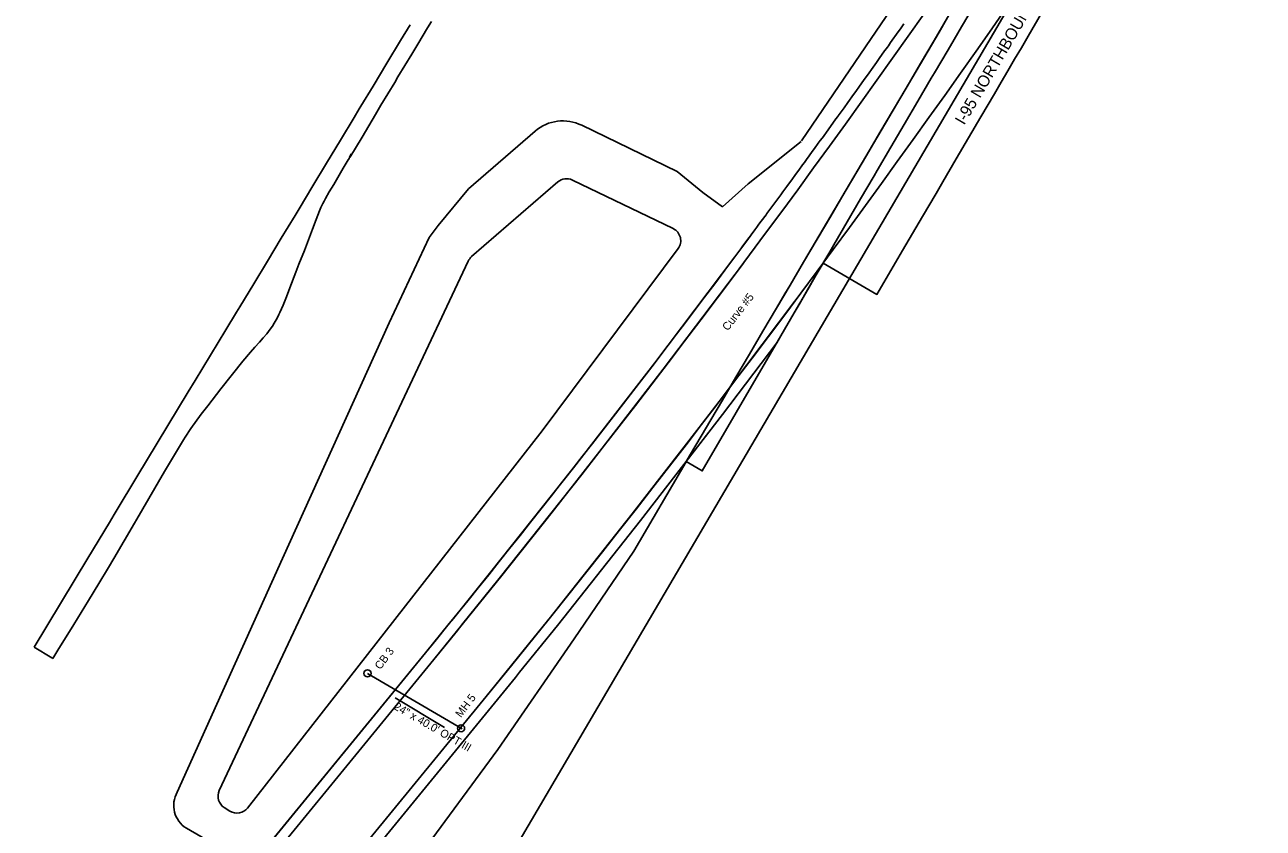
# Model space of a CAD drawing. Extents: x 1160458 to 1162290, y 615427 to 618737.
# Drawn here: x 1161573.3 to 1162037.4, y 617839 to 618140.3 of the extents above; entities that cross this region are included whole.
import ezdxf

# ---------------------------------------------------------------- set-up
doc = ezdxf.new("R2010")
doc.units = 0
for name, color, linetype in [('1', 7, 'Continuous'), ('ANNOTATION', 7, 'Continuous'), ('D_Drainage_Culvert', 7, 'Continuous'), ('D_Drainage_Ditch_Line', 7, 'Continuous'), ('D_Drainage_MH', 7, 'Continuous'), ('D_Drainage_Text', 7, 'Continuous'), ('D_Guardrail_Beam_Lt', 7, 'Continuous'), ('D_Roadway_Edge_Pavement', 7, 'Continuous'), ('D_Roadway_Edge_Shoulder', 7, 'Continuous'), ('D_Roadway_Edge_TW', 7, 'Continuous'), ('D_Slope_Cut', 7, 'Continuous'), ('D_Slope_Fill', 7, 'Continuous'), ('D_Text_Standard', 7, 'Continuous'), ('Old pavement area_not used', 7, 'Continuous'), ('Shoulder work for div plan (NB)', 7, 'Continuous'), ('Shoulder work for div plans (SB)', 7, 'Continuous')]:
    doc.layers.add(name, color=color, linetype=linetype)

msp = doc.modelspace()

# ---------------------------------------------------------------- linework, layer by layer
at = {"layer": '1'}
msp.add_line((1161209.81, 616899.51), (1162286.6, 618733.81), dxfattribs=at)
at = {"layer": 'D_Drainage_Culvert'}
msp.add_line((1161701.71, 617897.08), (1161737.14, 617876.33), dxfattribs=at)
at = {"layer": 'D_Drainage_Ditch_Line'}
for p, q in [((1161740.72, 618053.31), (1161773.05, 618081.31)), ((1161778.49, 618082.04), (1161816.28, 618063.82)), ((1161646.17, 617853.13), (1161739.47, 618051.66)), ((1161650.16, 617845.44), (1161648.04, 617846.77))]:
    msp.add_line(p, q, dxfattribs=at)
msp.add_lwpolyline([(1161818.11, 618056.33), (1161767.17, 617987.95), (1161656.76, 617846.59)], dxfattribs=at)
for centre, start, end in [((1161776.32, 618077.53), 64.2558, 130.8964), ((1161814.1, 618059.32), 323.3125, 64.2558), ((1161743.99, 618049.53), 130.8964, 154.8308), ((1161650.7, 617851), 154.8308, 237.8219), ((1161652.82, 617849.67), 237.8219, 322.0086)]:
    msp.add_arc(centre, 5, start, end, dxfattribs=at)
at = {"layer": 'D_Drainage_MH'}
for centre in [(1161701.71, 617897.08), (1161736.79, 617876.49)]:
    msp.add_circle(centre, 1.33, dxfattribs=at)
at = {"layer": 'D_Guardrail_Beam_Lt'}
msp.add_line((1161723.42, 617904.81), (1161637.37, 617799.61), dxfattribs=at)
msp.add_arc((1158484.81, 620553.82), 4184, 320.71863, 323.46992, dxfattribs=at)
at = {"layer": 'D_Roadway_Edge_Pavement'}
msp.add_line((1161872.48, 618050.9), (1161892.62, 618039.13), dxfattribs=at)
for points in [[(1161637.38, 617799.61), (1161723.43, 617904.81), (1161732.32, 617915.72), (1161733.89, 617917.65), (1161747.97, 617935.1), (1161778.91, 617974.13), (1161809.39, 618013.53), (1161839.39, 618053.29)], [(1161618.68, 617724.81), (1161646.49, 617760.08), (1161649.61, 617763.95), (1161650.23, 617764.73), (1161662.12, 617779.35), (1161748.17, 617884.56), (1161757.13, 617895.56), (1161758.72, 617897.51), (1161772.9, 617915.08), (1161804.08, 617954.41), (1161834.79, 617994.11), (1161855.07, 618020.99)]]:
    msp.add_lwpolyline(points, dxfattribs=at)
at = {"layer": 'D_Roadway_Edge_Shoulder'}
msp.add_lwpolyline([(1161837.36, 618050.57), (1161838.6, 618052.24), (1161839.39, 618053.3), (1161841.21, 618055.74), (1161841.61, 618056.28), (1161842.4, 618057.35), (1161844.61, 618060.31), (1161845.07, 618060.93), (1161845.41, 618061.39), (1161847.6, 618064.36), (1161848.4, 618065.44), (1161850.59, 618068.39), (1161851.06, 618069.03), (1161851.4, 618069.49), (1161852.85, 618071.46), (1161853.58, 618072.45), (1161854.39, 618073.54), (1161856.56, 618076.49), (1161857.36, 618077.59), (1161858.81, 618079.57), (1161859.53, 618080.55), (1161860.34, 618081.65), (1161862.5, 618084.6), (1161863.31, 618085.71), (1161864.75, 618087.69), (1161865.47, 618088.67), (1161866.28, 618089.78), (1161867.24, 618091.1), (1161868.42, 618092.73), (1161869.23, 618093.84), (1161870.67, 618095.82), (1161871.38, 618096.8), (1161872.09, 618097.77), (1161872.19, 618097.92), (1161874.33, 618100.87), (1161877.28, 618104.94), (1161877.98, 618105.92), (1161878.09, 618106.07), (1161880.3, 618109.13), (1161881.76, 618111.16), (1161883.85, 618114.08), (1161884.7, 618115.26), (1161886.16, 618117.29), (1161887.61, 618119.32), (1161889.7, 618122.25), (1161890.55, 618123.43), (1161892.46, 618126.12), (1161893.5, 618127.58), (1161895.53, 618130.43), (1161895.62, 618130.56), (1161896.57, 618131.89), (1161896.92, 618132.39), (1161897.74, 618133.55), (1161900.64, 618137.64), (1161901.43, 618138.75), (1161902.72, 618140.58)], dxfattribs=at)
at = {"layer": 'D_Roadway_Edge_TW'}
for points in [[(1161640.47, 617797.08), (1161726.52, 617902.28), (1161735.42, 617913.2), (1161736.99, 617915.14), (1161751.08, 617932.6), (1161782.05, 617971.67), (1161812.56, 618011.1), (1161842.58, 618050.88)], [(1161659.04, 617781.88), (1161745.09, 617887.08), (1161754.05, 617898.07), (1161755.62, 617900.01), (1161769.79, 617917.57), (1161800.95, 617956.87), (1161831.63, 617996.53), (1161861.85, 618036.57)]]:
    msp.add_lwpolyline(points, dxfattribs=at)
for radius in [4188, 4212]:
    msp.add_arc((1158484.81, 620553.82), radius, 320.71863, 329.58575, dxfattribs=at)
at = {"layer": 'D_Slope_Cut'}
for p, q in [((1161834.79, 618072.02), (1161844.39, 618080.57)), ((1161633.82, 617839.01), (1161646.1, 617831.93))]:
    msp.add_line(p, q, dxfattribs=at)
for points in [[(1161764.53, 618100.39), (1161739.5, 618078.71), (1161728.2, 618064.96), (1161724.84, 618060.51), (1161709.79, 618028.48), (1161669.91, 617940.09), (1161630.43, 617852.53)], [(1161834.79, 618072.02), (1161827.35, 618077.35), (1161817.81, 618085.28), (1161781.98, 618102.56)]]:
    msp.add_lwpolyline(points, dxfattribs=at)
for centre, radius, start, end in [((1161774.9, 618088.21), 16, 63.7426, 130.4032), ((1161639.16, 617847.54), 10.06, 150.2229, 237.9775)]:
    msp.add_arc(centre, radius, start, end, dxfattribs=at)
at = {"layer": 'D_Slope_Fill'}
msp.add_line((1161864.23, 618096.46), (1161844.39, 618080.57), dxfattribs=at)
for points in [[(1161864.33, 618096.78), (1161892.38, 618137.82), (1161920.38, 618178.92), (1161947.2, 618220.79), (1161974.76, 618262.22), (1162003.5, 618302.78), (1162031.65, 618343.82), (1162058.74, 618385.58), (1162080.66, 618419.35), (1162091.79, 618436.2), (1162091.79, 618436.2)], [(1161467.62, 617462.59), (1161495.86, 617503), (1161520.87, 617545.48), (1161546.51, 617587.64), (1161578.88, 617625.09), (1161605.67, 617666.51), (1161619.85, 617717.84), (1161649.13, 617757.97), (1161681.16, 617796.15), (1161720.89, 617828.25), (1161750.61, 617868.53), (1161779.17, 617910.05), (1161801.48, 617942.93), (1161821.11, 617976.43)]]:
    msp.add_lwpolyline(points, dxfattribs=at)
at = {"layer": 'D_Text_Standard'}
msp.add_line((1161712.08, 617887.96), (1161730.57, 617876.83), dxfattribs=at)
at = {"layer": 'Old pavement area_not used'}
for points in [[(1161919.14, 618142.92), (1161914.07, 618134.3), (1161908.99, 618125.68), (1161903.92, 618117.07), (1161898.84, 618108.45), (1161893.76, 618099.84), (1161888.69, 618091.22), (1161885.45, 618085.73), (1161880.37, 618077.11), (1161875.3, 618068.5), (1161870.22, 618059.88), (1161865.15, 618051.26), (1161860.07, 618042.65), (1161855, 618034.03), (1161849.93, 618025.41), (1161844.85, 618016.79), (1161839.78, 618008.18), (1161834.71, 617999.56), (1161830.36, 617992.17), (1161821.12, 617976.45)], [(1161855.09, 618021.01), (1161856.62, 618023.65), (1161861.65, 618032.3), (1161866.68, 618040.94), (1161869.91, 618046.49), (1161872.48, 618050.9), (1161892.62, 618039.13), (1161902.25, 618055.61), (1161909.73, 618068.41), (1161914.79, 618077.04), (1161917.31, 618081.35), (1161922.36, 618089.98), (1161926.98, 618097.88), (1161931.61, 618105.77), (1161936.66, 618114.4), (1161939.19, 618118.71), (1161941.71, 618123.02), (1161944.24, 618127.34), (1161946.77, 618131.65), (1161949.3, 618135.97), (1161954.35, 618144.59)], [(1161821.12, 617976.45), (1161834.8, 617994.12), (1161855.09, 618021.01)]]:
    msp.add_lwpolyline(points, dxfattribs=at)
at = {"layer": 'Shoulder work for div plan (NB)'}
msp.add_line((1161921.57, 618134.78), (1161921.57, 618134.78), dxfattribs=at)
for points in [[(1162008.98, 618296.98), (1162007.84, 618295), (1162002.84, 618286.34), (1161997.84, 618277.68), (1161992.87, 618269.04), (1161987.86, 618260.38), (1161985.49, 618256.3), (1161980.47, 618247.65), (1161975.44, 618239.01), (1161970.4, 618230.37), (1161968.95, 618227.89), (1161963.91, 618219.25), (1161958.86, 618210.62), (1161953.81, 618201.98), (1161948.76, 618193.35), (1161946.83, 618190.06), (1161941.78, 618181.44), (1161936.72, 618172.81), (1161933.64, 618167.57), (1161928.57, 618158.95), (1161923.5, 618150.33), (1161919.14, 618142.92), (1161915.96, 618137.52)], [(1161921.57, 618134.78), (1161924.35, 618139.51), (1161929.4, 618148.14)], [(1161915.96, 618137.52), (1161891.35, 618095.75), (1161866.74, 618053.97)], [(1161872.38, 618050.74), (1161874.93, 618055.11), (1161876.44, 618057.7), (1161881.48, 618066.34), (1161886.53, 618074.97), (1161891.57, 618083.6), (1161892.78, 618085.67), (1161897.83, 618094.3), (1161902.89, 618102.92), (1161907.95, 618111.55), (1161913.01, 618120.18), (1161914.22, 618122.25), (1161919.28, 618130.87), (1161921.57, 618134.78)], [(1161866.74, 618053.97), (1161865.15, 618051.26), (1161860.07, 618042.65), (1161858.12, 618039.32)], [(1161863.43, 618035.36), (1161866.66, 618040.93), (1161869.9, 618046.47), (1161872.38, 618050.74)], [(1161858.12, 618039.32), (1161855, 618034.03), (1161849.93, 618025.41), (1161844.85, 618016.79), (1161839.78, 618008.18), (1161834.71, 617999.56), (1161830.36, 617992.17), (1161821.12, 617976.45)], [(1161852.58, 618016.69), (1161856.61, 618023.64), (1161861.64, 618032.28), (1161863.43, 618035.36)], [(1161821.12, 617976.45), (1161827.14, 617972.95), (1161852.58, 618016.69)]]:
    msp.add_lwpolyline(points, dxfattribs=at)
at = {"layer": 'Shoulder work for div plans (SB)'}
for p, q in [((1161724.24, 618139.12), (1161725.69, 618141.52)), ((1161720.52, 618132.96), (1161724.24, 618139.12)), ((1161706.76, 618110.09), (1161711.91, 618118.67)), ((1161698.63, 618108.69), (1161696.72, 618105.52)), ((1161699.26, 618109.72), (1161698.63, 618108.69)), ((1161704.7, 618106.64), (1161706.76, 618110.09)), ((1161696.72, 618105.52), (1161691.56, 618096.95)), ((1161699.65, 618098.15), (1161704.7, 618106.64)), ((1161691.56, 618096.95), (1161686.4, 618088.39)), ((1161695.05, 618090.44), (1161699.65, 618098.15)), ((1161695.64, 618091.85), (1161695.05, 618090.44)), ((1161695.38, 618091.41), (1161695.64, 618091.85)), ((1161686.4, 618088.39), (1161681.24, 618079.83)), ((1161689.04, 618080.39), (1161692.65, 618086.44)), ((1161692.65, 618086.44), (1161694.52, 618089.56)), ((1161694.52, 618089.56), (1161694.64, 618089.76)), ((1161681.24, 618079.83), (1161676.07, 618071.26)), ((1161686.01, 618075.17), (1161687.4, 618077.6)), ((1161687.4, 618077.6), (1161689.04, 618080.39)), ((1161684.96, 618073.24), (1161685.43, 618074.14)), ((1161685.43, 618074.14), (1161686.01, 618075.17)), ((1161669.41, 618060.23), (1161664.24, 618051.67)), ((1161676.01, 618050.48), (1161678.04, 618055.63)), ((1161667.48, 618029.57), (1161667.83, 618030.22)), ((1161659.51, 618019.37), (1161661.21, 618021.27)), ((1161661.21, 618021.27), (1161662.6, 618022.84)), ((1161657.87, 618017.53), (1161659.51, 618019.37)), ((1161641.82, 617997.4), (1161646.71, 618003.73)), ((1161639.41, 617994.29), (1161641.82, 617997.4)), ((1161625.68, 617972.76), (1161632.7, 617984.59)), ((1161615.32, 617970.77), (1161607.57, 617957.93)), ((1161619.77, 617962.67), (1161625.68, 617972.76)), ((1161615.28, 617954.92), (1161619.77, 617962.67)), ((1161607.57, 617957.93), (1161607.57, 617957.93)), ((1161614.4, 617953.41), (1161615.28, 617954.92)), ((1161585.69, 617905.74), (1161591.61, 617915.36)), ((1161576.79, 617906.86), (1161583.42, 617902.88)), ((1161583.78, 617902.66), (1161585.69, 617905.74)), ((1161583.42, 617902.88), (1161583.78, 617902.66))]:
    msp.add_line(p, q, dxfattribs=at)
for points in [[(1161717.68, 618140.26), (1161714.13, 618134.38), (1161708.96, 618125.81)], [(1161711.91, 618118.67), (1161713.11, 618120.67), (1161718.27, 618129.24), (1161720.52, 618132.96)], [(1161708.96, 618125.81), (1161703.8, 618117.25), (1161699.26, 618109.72)], [(1161682.52, 618067.27), (1161683.69, 618070.45), (1161684.24, 618071.76), (1161684.96, 618073.24)], [(1161676.07, 618071.26), (1161674.58, 618068.79), (1161669.41, 618060.23)], [(1161678.04, 618055.63), (1161681.14, 618063.6), (1161682.52, 618067.27)], [(1161664.24, 618051.67), (1161659.07, 618043.12), (1161653.89, 618034.56)], [(1161671.36, 618038.28), (1161672.64, 618041.57), (1161674.86, 618047.46), (1161676.01, 618050.48)], [(1161653.89, 618034.56), (1161652.64, 618032.49), (1161648.67, 618025.93)], [(1161667.83, 618030.22), (1161668.54, 618031.64), (1161668.91, 618032.43), (1161669.49, 618033.72), (1161670.09, 618035.14), (1161671.36, 618038.28)], [(1161648.67, 618025.93), (1161637.11, 618006.83), (1161637.11, 618006.83), (1161634.56, 618002.62), (1161615.32, 617970.77)], [(1161662.6, 618022.84), (1161663.94, 618024.43), (1161664.57, 618025.21), (1161665.6, 618026.58), (1161666.09, 618027.28)], [(1161666.09, 618027.28), (1161666.79, 618028.38), (1161667.48, 618029.57)], [(1161646.71, 618003.73), (1161655.04, 618014.18), (1161657.87, 618017.53)], [(1161632.7, 617984.59), (1161633.35, 617985.6), (1161635.56, 617988.94), (1161639.41, 617994.29)], [(1161607.57, 617957.93), (1161607.57, 617957.93), (1161606.82, 617956.7), (1161604.98, 617953.65), (1161596.93, 617940.3), (1161596.93, 617940.3), (1161576.79, 617906.86)], [(1161604.62, 617936.73), (1161606.63, 617940.12), (1161614.4, 617953.41)], [(1161591.61, 617915.36), (1161597.18, 617924.45), (1161601.05, 617930.8), (1161604.62, 617936.73)]]:
    msp.add_lwpolyline(points, dxfattribs=at)
msp.add_arc((1165538.1, 616366.76), 4212, 155.82908, 155.8537, dxfattribs=at)

# ---------------------------------------------------------------- texts
at = {"layer": 'ANNOTATION'}
msp.add_text('Curve #5', height=3, rotation=52.1458, dxfattribs=at).set_placement((1161836.74, 618025.28))
at = {"layer": 'D_Drainage_Text'}
for s, rotation, p in [('CB 3', 53.228, (1161706.52, 617898.25)), ('24" x 40.0\' OPT III', 330.1239, (1161711.34, 617883.8)), ('MH 5', 53.0696, (1161736.76, 617880.26))]:
    msp.add_text(s, height=3, rotation=rotation, dxfattribs=at).set_placement(p)
at = {"layer": 'D_Text_Standard'}
msp.add_text('I-95 NORTHBOUND', height=4.375, rotation=59.6079, dxfattribs=at).set_placement((1161925.34, 618102.38))

doc.saveas('drawing.dxf')
